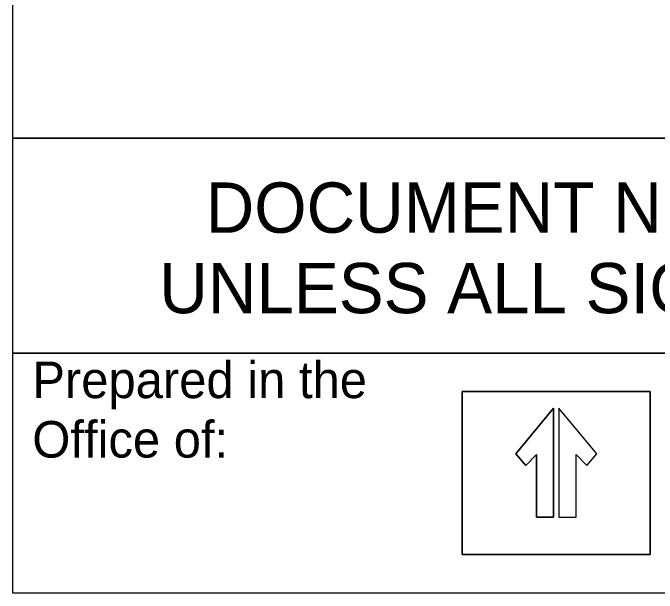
# Model space of a CAD drawing. Extents: x 2046816 to 2049224, y 578750 to 586986.
# Drawn here: x 2049015.4 to 2049081.1, y 586728.4 to 586787.6 of the extents above; entities that cross this region are included whole.
import ezdxf

# ---------------------------------------------------------------- set-up
doc = ezdxf.new("R2010")
doc.units = 0
for name, color, linetype in [('Old_Level_2', 7, 'Continuous'), ('Sheet Block Title CELL', 7, 'Continuous'), ('Sheet Sticker Exception Certification CELL', 7, 'Continuous')]:
    doc.layers.add(name, color=color, linetype=linetype)

msp = doc.modelspace()

# ---------------------------------------------------------------- linework, layer by layer
at = {"layer": 'Old_Level_2'}
msp.add_lwpolyline([(2049015.389, 586886.205), (2049202.335, 586886.205), (2049202.335, 586774.828), (2049015.389, 586774.828)], close=True, dxfattribs=at)
at = {"layer": 'Sheet Block Title CELL'}
for points in [[(2049015.389, 586752.898), (2049202.164, 586752.898), (2049202.164, 586728.385), (2049015.389, 586728.385)], [(2049061.232, 586748.971), (2049080.424, 586748.971), (2049080.424, 586732.313), (2049061.232, 586732.313)], [(2049071.108, 586747.267), (2049071.108, 586736.129), (2049072.863, 586736.129), (2049072.863, 586742.553), (2049073.949, 586741.403), (2049074.971, 586742.623)]]:
    msp.add_lwpolyline(points, close=True, dxfattribs=at)
for points in [[(2049080.424, 586748.971), (2049061.232, 586748.971), (2049061.232, 586732.313), (2049080.424, 586732.313), (2049080.424, 586748.971)], [(2049070.568, 586747.267), (2049070.568, 586736.129), (2049068.814, 586736.129), (2049068.814, 586742.553), (2049067.727, 586741.403), (2049066.705, 586742.623), (2049070.568, 586747.267)], [(2049066.705, 586742.623), (2049067.727, 586741.403), (2049068.814, 586742.553), (2049068.814, 586736.129), (2049070.568, 586736.129), (2049070.568, 586747.267), (2049066.705, 586742.623)], [(2049071.108, 586747.267), (2049071.108, 586736.129), (2049072.863, 586736.129), (2049072.863, 586742.553), (2049073.949, 586741.403), (2049074.971, 586742.623), (2049071.108, 586747.267)]]:
    msp.add_lwpolyline(points, dxfattribs=at)
at = {"layer": 'Sheet Sticker Exception Certification CELL'}
for p, q in [((2049015.389, 586752.898), (2049015.389, 586774.84)), ((2049015.389, 586774.84), (2049202.164, 586774.84)), ((2049202.164, 586752.898), (2049015.389, 586752.898))]:
    msp.add_line(p, q, dxfattribs=at)

# ---------------------------------------------------------------- texts
at = {"layer": 'Sheet Block Title CELL'}
for s, height, p in [('Prepared in the ', 3.73551, (2049017.37, 586748.292)), ('Office of:', 3.7355, (2049017.37, 586742.222))]:
    msp.add_text(s, height=height, rotation=360, dxfattribs=at).set_placement(p)
at = {"layer": 'Sheet Sticker Exception Certification CELL'}
for s, p in [('DOCUMENT NOT CONSIDERED FINAL', (2049035.062, 586765.18)), ('UNLESS ALL SIGNATURES COMPLETED', (2049030.327, 586756.964))]:
    msp.add_text(s, height=5.13536, dxfattribs=at).set_placement(p)

doc.saveas('drawing.dxf')
